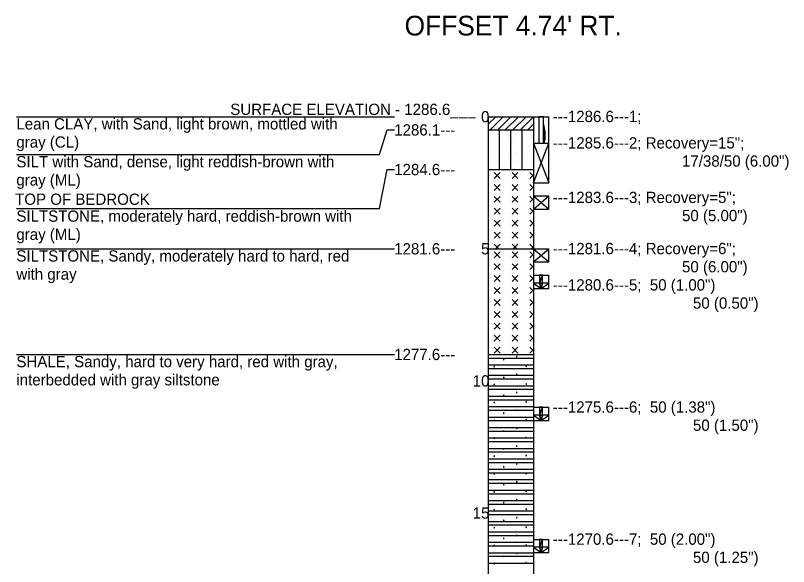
# Model space of a CAD drawing. Extents: x -6 to 173, y 24 to 64.
# Drawn here: x 152.92 to 161.44, y 44.54 to 50.61 of the extents above; entities that cross this region are included whole.
import ezdxf

# ---------------------------------------------------------------- set-up
doc = ezdxf.new("R2010")
doc.units = 0

# ---------------------------------------------------------------- blocks, each defined once
blk = doc.blocks.new('POINT_DISPLAY')
blk.add_line((0, 0), (0, 0))

msp = doc.modelspace()

# ---------------------------------------------------------------- linework, layer by layer
for points in [[(152.9304, 49.4948), (157.097, 49.4948)], [(158.1273, 49.4115), (158.2107, 49.4948)], [(158.1273, 49.4948), (158.794, 49.4948)], [(158.1273, 49.4948), (158.1273, 39.0297)], [(158.1487, 49.3495), (158.294, 49.4948)], [(158.232, 49.3495), (158.3773, 49.4948)], [(158.3153, 49.3495), (158.4607, 49.4948)], [(158.3987, 49.3495), (158.544, 49.4948)], [(158.482, 49.3495), (158.6273, 49.4948)], [(158.6273, 49.4948), (158.6273, 39.0297)], [(158.794, 49.2041), (158.794, 49.4948)], [(158.5653, 49.3495), (158.6273, 49.4115)], [(152.9304, 49.0781), (156.9304, 49.0781), (157.0137, 49.3495), (157.097, 49.3495)], [(158.1273, 49.3495), (158.6273, 49.3495)], [(158.2523, 48.9134), (158.2523, 49.3495)], [(158.3773, 48.9134), (158.3773, 49.3495)], [(158.5023, 48.9134), (158.5023, 49.3495)], [(158.6273, 49.2041), (158.794, 49.2041)], [(158.6273, 49.2041), (158.794, 48.7681)], [(158.6273, 48.7681), (158.794, 49.2041)], [(158.6273, 49.2041), (158.794, 49.2041)], [(158.794, 48.7681), (158.794, 49.2041)], [(152.9304, 48.4833), (156.9304, 48.4833), (157.0137, 48.9134), (157.097, 48.9134)], [(158.1273, 48.9134), (158.6273, 48.9134)], [(158.2586, 48.8806), (158.193, 48.815)], [(158.193, 48.8806), (158.2586, 48.815)], [(158.4554, 48.8806), (158.3898, 48.815)], [(158.3898, 48.8806), (158.4554, 48.815)], [(158.5867, 48.8806), (158.6273, 48.8399)], [(158.6273, 48.8557), (158.5867, 48.815)], [(158.2586, 48.7494), (158.193, 48.6838)], [(158.193, 48.7494), (158.2586, 48.6838)], [(158.4554, 48.7494), (158.3898, 48.6838)], [(158.3898, 48.7494), (158.4554, 48.6838)], [(158.5867, 48.7494), (158.6273, 48.7087)], [(158.6273, 48.7244), (158.5867, 48.6838)], [(158.6273, 48.7681), (158.794, 48.7681)], [(158.2586, 48.6181), (158.193, 48.5525)], [(158.193, 48.6181), (158.2586, 48.5525)], [(158.4554, 48.6181), (158.3898, 48.5525)], [(158.3898, 48.6181), (158.4554, 48.5525)], [(158.5867, 48.6181), (158.6273, 48.5775)], [(158.6273, 48.5932), (158.5867, 48.5525)], [(158.6273, 48.6227), (158.794, 48.4774)], [(158.6273, 48.4774), (158.794, 48.6227)], [(158.6273, 48.6227), (158.794, 48.6227)], [(158.794, 48.4774), (158.794, 48.6227)], [(158.2586, 48.4869), (158.193, 48.4213)], [(158.193, 48.4869), (158.2586, 48.4213)], [(158.4554, 48.4869), (158.3898, 48.4213)], [(158.3898, 48.4869), (158.4554, 48.4213)], [(158.5867, 48.4869), (158.6273, 48.4462)], [(158.6273, 48.462), (158.5867, 48.4213)], [(158.6273, 48.4774), (158.794, 48.4774)], [(158.2586, 48.3557), (158.193, 48.2901)], [(158.193, 48.3557), (158.2586, 48.2901)], [(158.4554, 48.3557), (158.3898, 48.2901)], [(158.3898, 48.3557), (158.4554, 48.2901)], [(158.5867, 48.3557), (158.6273, 48.315)], [(158.6273, 48.3307), (158.5867, 48.2901)], [(158.2586, 48.2244), (158.193, 48.1588)], [(158.193, 48.2244), (158.2586, 48.1588)], [(158.4554, 48.2244), (158.3898, 48.1588)], [(158.3898, 48.2244), (158.4554, 48.1588)], [(158.5867, 48.2244), (158.6273, 48.1838)], [(158.6273, 48.1995), (158.5867, 48.1588)], [(152.9304, 48.0413), (157.097, 48.0413)], [(158.1273, 48.0413), (158.6273, 48.0413)], [(158.193, 48.0932), (158.2448, 48.0413)], [(158.2586, 48.0932), (158.2067, 48.0413)], [(158.3898, 48.0932), (158.4417, 48.0413)], [(158.4554, 48.0932), (158.4035, 48.0413)], [(158.5867, 48.0932), (158.6123, 48.0676), (158.6273, 48.0525)], [(158.6273, 48.0683), (158.6175, 48.0585), (158.6004, 48.0413)], [(158.6273, 48.0413), (158.794, 47.896)], [(158.6273, 47.896), (158.794, 48.0413)], [(158.6273, 48.0413), (158.794, 48.0413)], [(158.794, 47.896), (158.794, 48.0413)], [(158.2586, 48.0085), (158.193, 47.9429)], [(158.193, 48.0085), (158.2586, 47.9429)], [(158.4554, 48.0085), (158.3898, 47.9429)], [(158.3898, 48.0085), (158.4554, 47.9429)], [(158.5867, 48.0085), (158.6273, 47.9678)], [(158.6273, 47.9836), (158.5867, 47.9429)], [(158.2586, 47.8773), (158.193, 47.8117)], [(158.193, 47.8773), (158.2586, 47.8117)], [(158.4554, 47.8773), (158.3898, 47.8117)], [(158.3898, 47.8773), (158.4554, 47.8117)], [(158.5867, 47.8773), (158.6273, 47.8366)], [(158.6273, 47.896), (158.794, 47.896)], [(158.6273, 47.8523), (158.5867, 47.8117)], [(158.2586, 47.7461), (158.193, 47.6804)], [(158.193, 47.7461), (158.2586, 47.6804)], [(158.4554, 47.7461), (158.3898, 47.6804)], [(158.3898, 47.7461), (158.4554, 47.6804)], [(158.5867, 47.7461), (158.6273, 47.7054)], [(158.6273, 47.7211), (158.5867, 47.6804)], [(158.6273, 47.7506), (158.794, 47.7506)], [(158.794, 47.6053), (158.794, 47.7506)], [(158.2586, 47.6148), (158.193, 47.5492)], [(158.193, 47.6148), (158.2586, 47.5492)], [(158.4554, 47.6148), (158.3898, 47.5492)], [(158.3898, 47.6148), (158.4554, 47.5492)], [(158.5867, 47.6148), (158.6273, 47.5741)], [(158.6273, 47.6053), (158.794, 47.6053)], [(158.6273, 47.5899), (158.5867, 47.5492)], [(158.2586, 47.4836), (158.193, 47.418)], [(158.193, 47.4836), (158.2586, 47.418)], [(158.4554, 47.4836), (158.3898, 47.418)], [(158.3898, 47.4836), (158.4554, 47.418)], [(158.5867, 47.4836), (158.6273, 47.4429)], [(158.6273, 47.4586), (158.5867, 47.418)], [(158.2586, 47.3523), (158.193, 47.2867)], [(158.193, 47.3523), (158.2586, 47.2867)], [(158.4554, 47.3523), (158.3898, 47.2867)], [(158.3898, 47.3523), (158.4554, 47.2867)], [(158.5867, 47.3523), (158.6273, 47.3117)], [(158.6273, 47.3274), (158.5867, 47.2867)], [(158.2586, 47.2211), (158.193, 47.1555)], [(158.193, 47.2211), (158.2586, 47.1555)], [(158.4554, 47.2211), (158.3898, 47.1555)], [(158.3898, 47.2211), (158.4554, 47.1555)], [(158.5867, 47.2211), (158.6273, 47.1804)], [(158.6273, 47.1962), (158.5867, 47.1555)], [(158.2586, 47.0899), (158.193, 47.0243)], [(158.193, 47.0899), (158.2586, 47.0243)], [(158.4554, 47.0899), (158.3898, 47.0243)], [(158.3898, 47.0899), (158.4554, 47.0243)], [(158.5867, 47.0899), (158.6273, 47.0492)], [(158.6273, 47.0649), (158.5867, 47.0243)], [(158.2586, 46.9586), (158.193, 46.893)], [(158.193, 46.9586), (158.2586, 46.893)], [(158.4554, 46.9586), (158.3898, 46.893)], [(158.3898, 46.9586), (158.4554, 46.893)], [(158.5867, 46.9586), (158.5976, 46.9477), (158.6273, 46.918)], [(158.6273, 46.9337), (158.6107, 46.9171), (158.5867, 46.893)], [(152.9304, 46.8785), (157.097, 46.8785)], [(158.1273, 46.8785), (158.6273, 46.8785)], [(158.1273, 46.8785), (158.6273, 46.8785)], [(158.1273, 46.8392), (158.6273, 46.8392)], [(158.445, 46.8546), (158.4434, 46.8574), (158.4401, 46.8574), (158.4384, 46.8546), (158.4401, 46.8518), (158.4434, 46.8518), (158.445, 46.8546)], [(158.1273, 46.7637), (158.6273, 46.7637)], [(158.3024, 46.8227), (158.3008, 46.8256), (158.2975, 46.8256), (158.2958, 46.8228), (158.2975, 46.8199), (158.3008, 46.8199), (158.3024, 46.8227)], [(158.5505, 46.7503), (158.5489, 46.7531), (158.5456, 46.7531), (158.5439, 46.7503), (158.5456, 46.7474), (158.5489, 46.7474), (158.5505, 46.7503)], [(158.1273, 46.7243), (158.6273, 46.7243)], [(158.1977, 46.7438), (158.1961, 46.7466), (158.1928, 46.7466), (158.1912, 46.7438), (158.1928, 46.7409), (158.1961, 46.7409), (158.1977, 46.7438)], [(158.1273, 46.6489), (158.6273, 46.6489)], [(158.1273, 46.6095), (158.6273, 46.6095)], [(158.3024, 46.6258), (158.3008, 46.6287), (158.2975, 46.6287), (158.2958, 46.6259), (158.2975, 46.623), (158.3008, 46.623), (158.3024, 46.6258)], [(158.445, 46.6577), (158.4434, 46.6606), (158.4401, 46.6606), (158.4384, 46.6577), (158.4401, 46.6549), (158.4434, 46.6549), (158.445, 46.6577)], [(158.1273, 46.534), (158.6273, 46.534)], [(158.1977, 46.5469), (158.1961, 46.5497), (158.1928, 46.5497), (158.1912, 46.5469), (158.1928, 46.544), (158.1961, 46.544), (158.1977, 46.5469)], [(158.5505, 46.5534), (158.5489, 46.5563), (158.5456, 46.5563), (158.5439, 46.5534), (158.5456, 46.5506), (158.5489, 46.5506), (158.5505, 46.5534)], [(158.1273, 46.4947), (158.6273, 46.4947)], [(158.1273, 46.4192), (158.6273, 46.4192)], [(158.3024, 46.429), (158.3008, 46.4319), (158.2975, 46.4319), (158.2958, 46.4291), (158.2975, 46.4262), (158.3008, 46.4262), (158.3024, 46.429)], [(158.445, 46.4609), (158.4434, 46.4637), (158.4401, 46.4637), (158.4384, 46.4609), (158.4401, 46.4581), (158.4434, 46.4581), (158.445, 46.4609)], [(158.1273, 46.3798), (158.6273, 46.3798)], [(158.1977, 46.3501), (158.1961, 46.3529), (158.1928, 46.3529), (158.1912, 46.3501), (158.1928, 46.3472), (158.1961, 46.3472), (158.1977, 46.3501)], [(158.5505, 46.3566), (158.5489, 46.3594), (158.5456, 46.3594), (158.5439, 46.3566), (158.5456, 46.3537), (158.5489, 46.3537), (158.5505, 46.3566)], [(158.1273, 46.3044), (158.6273, 46.3044)], [(158.1273, 46.265), (158.6273, 46.265)], [(158.445, 46.264), (158.4434, 46.2669), (158.4401, 46.2669), (158.4384, 46.264), (158.4401, 46.2612), (158.4434, 46.2612), (158.445, 46.264)], [(158.6273, 46.2971), (158.794, 46.2971)], [(158.794, 46.1518), (158.794, 46.2971)], [(158.1273, 46.1896), (158.6273, 46.1896)], [(158.1977, 46.1532), (158.1961, 46.156), (158.1928, 46.156), (158.1912, 46.1532), (158.1928, 46.1503), (158.1961, 46.1503), (158.1977, 46.1532)], [(158.3024, 46.2321), (158.3008, 46.235), (158.2975, 46.235), (158.2958, 46.2322), (158.2975, 46.2293), (158.3008, 46.2293), (158.3024, 46.2321)], [(158.5505, 46.1597), (158.5489, 46.1626), (158.5456, 46.1626), (158.5439, 46.1597), (158.5456, 46.1569), (158.5489, 46.1569), (158.5505, 46.1597)], [(158.1273, 46.1502), (158.6273, 46.1502)], [(158.1273, 46.0747), (158.6273, 46.0747)], [(158.445, 46.0672), (158.4434, 46.07), (158.4401, 46.07), (158.4384, 46.0672), (158.4401, 46.0644), (158.4434, 46.0644), (158.445, 46.0672)], [(158.6273, 46.1518), (158.794, 46.1518)], [(158.1273, 46.0354), (158.6273, 46.0354)], [(158.3024, 46.0353), (158.3008, 46.0382), (158.2975, 46.0382), (158.2958, 46.0354), (158.2975, 46.0325), (158.3008, 46.0325), (158.3024, 46.0353)], [(158.1273, 45.9599), (158.6273, 45.9599)], [(158.1273, 45.9205), (158.6273, 45.9205)], [(158.1977, 45.9564), (158.1961, 45.9592), (158.1928, 45.9592), (158.1912, 45.9564), (158.1928, 45.9535), (158.1961, 45.9535), (158.1977, 45.9564)], [(158.5505, 45.9629), (158.5489, 45.9657), (158.5456, 45.9657), (158.5439, 45.9629), (158.5456, 45.96), (158.5489, 45.96), (158.5505, 45.9629)], [(158.1273, 45.8451), (158.6273, 45.8451)], [(158.3024, 45.8384), (158.3008, 45.8413), (158.2975, 45.8413), (158.2958, 45.8385), (158.2975, 45.8356), (158.3008, 45.8356), (158.3024, 45.8384)], [(158.445, 45.8703), (158.4434, 45.8732), (158.4401, 45.8732), (158.4384, 45.8703), (158.4401, 45.8675), (158.4434, 45.8675), (158.445, 45.8703)], [(158.1273, 45.8057), (158.6273, 45.8057)], [(158.1273, 45.7302), (158.6273, 45.7302)], [(158.1977, 45.7595), (158.1961, 45.7623), (158.1928, 45.7623), (158.1912, 45.7595), (158.1928, 45.7566), (158.1961, 45.7566), (158.1977, 45.7595)], [(158.5505, 45.766), (158.5489, 45.7689), (158.5456, 45.7689), (158.5439, 45.766), (158.5456, 45.7632), (158.5489, 45.7632), (158.5505, 45.766)], [(158.1273, 45.6909), (158.6273, 45.6909)], [(158.3024, 45.6416), (158.3008, 45.6445), (158.2975, 45.6445), (158.2958, 45.6417), (158.2975, 45.6388), (158.3008, 45.6388), (158.3024, 45.6416)], [(158.445, 45.6735), (158.4434, 45.6763), (158.4401, 45.6763), (158.4384, 45.6735), (158.4401, 45.6707), (158.4434, 45.6707), (158.445, 45.6735)], [(158.1273, 45.6154), (158.6273, 45.6154)], [(158.1273, 45.576), (158.6273, 45.576)], [(158.1977, 45.5627), (158.1961, 45.5655), (158.1928, 45.5655), (158.1912, 45.5627), (158.1928, 45.5598), (158.1961, 45.5598), (158.1977, 45.5627)], [(158.5505, 45.5692), (158.5489, 45.572), (158.5456, 45.572), (158.5439, 45.5692), (158.5456, 45.5663), (158.5489, 45.5663), (158.5505, 45.5692)], [(158.1273, 45.5006), (158.6273, 45.5006)], [(158.445, 45.4766), (158.4434, 45.4795), (158.4401, 45.4795), (158.4384, 45.4766), (158.4401, 45.4738), (158.4434, 45.4738), (158.445, 45.4766)], [(158.1273, 45.4612), (158.6273, 45.4612)], [(158.3024, 45.4447), (158.3008, 45.4476), (158.2975, 45.4476), (158.2958, 45.4448), (158.2975, 45.4419), (158.3008, 45.4419), (158.3024, 45.4447)], [(158.1273, 45.3858), (158.6273, 45.3858)], [(158.1273, 45.3464), (158.6273, 45.3464)], [(158.1977, 45.3658), (158.1961, 45.3686), (158.1928, 45.3686), (158.1912, 45.3658), (158.1928, 45.3629), (158.1961, 45.3629), (158.1977, 45.3658)], [(158.5505, 45.3723), (158.5489, 45.3752), (158.5456, 45.3752), (158.5439, 45.3723), (158.5456, 45.3695), (158.5489, 45.3695), (158.5505, 45.3723)], [(158.1273, 45.2709), (158.6273, 45.2709)], [(158.1273, 45.2316), (158.6273, 45.2316)], [(158.3024, 45.2479), (158.3008, 45.2508), (158.2975, 45.2508), (158.2958, 45.248), (158.2975, 45.2451), (158.3008, 45.2451), (158.3024, 45.2479)], [(158.445, 45.2798), (158.4434, 45.2826), (158.4401, 45.2826), (158.4384, 45.2798), (158.4401, 45.277), (158.4434, 45.277), (158.445, 45.2798)], [(158.1273, 45.1561), (158.6273, 45.1561)], [(158.1977, 45.169), (158.1961, 45.1718), (158.1928, 45.1718), (158.1912, 45.169), (158.1928, 45.1661), (158.1961, 45.1661), (158.1977, 45.169)], [(158.5505, 45.1755), (158.5489, 45.1783), (158.5456, 45.1783), (158.5439, 45.1755), (158.5456, 45.1726), (158.5489, 45.1726), (158.5505, 45.1755)], [(158.1273, 45.1167), (158.6273, 45.1167)], [(158.3024, 45.051), (158.3008, 45.0539), (158.2975, 45.0539), (158.2958, 45.0511), (158.2975, 45.0482), (158.3008, 45.0482), (158.3024, 45.051)], [(158.445, 45.0829), (158.4434, 45.0858), (158.4401, 45.0858), (158.4384, 45.0829), (158.4401, 45.0801), (158.4434, 45.0801), (158.445, 45.0829)], [(158.1273, 45.0413), (158.6273, 45.0413)], [(158.1273, 45.0019), (158.6273, 45.0019)], [(158.1977, 44.9721), (158.1961, 44.9749), (158.1928, 44.9749), (158.1912, 44.9721), (158.1928, 44.9692), (158.1961, 44.9692), (158.1977, 44.9721)], [(158.5505, 44.9786), (158.5489, 44.9815), (158.5456, 44.9815), (158.5439, 44.9786), (158.5456, 44.9758), (158.5489, 44.9758), (158.5505, 44.9786)], [(158.1273, 44.9264), (158.6273, 44.9264)], [(158.1273, 44.8871), (158.6273, 44.8871)], [(158.445, 44.8861), (158.4434, 44.8889), (158.4401, 44.8889), (158.4384, 44.8861), (158.4401, 44.8833), (158.4434, 44.8833), (158.445, 44.8861)], [(158.1273, 44.8116), (158.6273, 44.8116)], [(158.3024, 44.8542), (158.3008, 44.8571), (158.2975, 44.8571), (158.2958, 44.8543), (158.2975, 44.8514), (158.3008, 44.8514), (158.3024, 44.8542)], [(158.6273, 44.8437), (158.794, 44.8437)], [(158.794, 44.6983), (158.794, 44.8437)], [(158.1273, 44.7722), (158.6273, 44.7722)], [(158.1977, 44.7753), (158.1961, 44.7781), (158.1928, 44.7781), (158.1912, 44.7753), (158.1928, 44.7724), (158.1961, 44.7724), (158.1977, 44.7753)], [(158.5505, 44.7818), (158.5489, 44.7846), (158.5456, 44.7846), (158.5439, 44.7818), (158.5456, 44.7789), (158.5489, 44.7789), (158.5505, 44.7818)], [(158.1273, 44.6968), (158.6273, 44.6968)], [(158.1273, 44.6574), (158.6273, 44.6574)], [(158.3024, 44.6573), (158.3008, 44.6602), (158.2975, 44.6602), (158.2958, 44.6574), (158.2975, 44.6545), (158.3008, 44.6545), (158.3024, 44.6573)], [(158.445, 44.6892), (158.4434, 44.6921), (158.4401, 44.6921), (158.4384, 44.6892), (158.4401, 44.6864), (158.4434, 44.6864), (158.445, 44.6892)], [(158.6273, 44.6983), (158.794, 44.6983)], [(158.1273, 44.5819), (158.6273, 44.5819)], [(158.1977, 44.5784), (158.1961, 44.5812), (158.1928, 44.5812), (158.1912, 44.5784), (158.1928, 44.5755), (158.1961, 44.5755), (158.1977, 44.5784)], [(158.5505, 44.5849), (158.5489, 44.5878), (158.5456, 44.5878), (158.5439, 44.5849), (158.5456, 44.5821), (158.5489, 44.5821), (158.5505, 44.5849)]]:
    msp.add_lwpolyline(points)
for points in [[(158.6857, 49.4948), (158.6857, 49.2041), (158.7357, 49.2041), (158.7357, 49.4948)], [(158.7503, 49.3281), (158.7443, 49.3698), (158.7357, 49.4098), (158.7503, 49.3281)], [(158.7357, 49.4098), (158.7357, 49.2041), (158.7503, 49.3281), (158.7357, 49.4098)], [(158.7357, 49.2041), (158.7503, 49.2448), (158.7503, 49.3281), (158.7357, 49.2041)], [(158.7503, 49.2448), (158.7523, 49.2865), (158.7503, 49.3281), (158.7503, 49.2448)], [(158.7357, 49.2041), (158.7445, 49.2041), (158.7503, 49.2448), (158.7357, 49.2041)], [(158.694, 47.6634), (158.7273, 47.6634), (158.7273, 47.7506), (158.694, 47.6634)], [(158.694, 47.6634), (158.7273, 47.7506), (158.694, 47.7506), (158.694, 47.6634)], [(158.694, 47.6634), (158.6273, 47.6634), (158.7107, 47.6053), (158.694, 47.6634)], [(158.694, 47.6634), (158.7107, 47.6053), (158.7273, 47.6634), (158.694, 47.6634)], [(158.7107, 47.6053), (158.794, 47.6634), (158.7273, 47.6634), (158.7107, 47.6053)], [(158.694, 46.2099), (158.7273, 46.2099), (158.7273, 46.2971), (158.694, 46.2099)], [(158.694, 46.2099), (158.7273, 46.2971), (158.694, 46.2971), (158.694, 46.2099)], [(158.694, 46.2099), (158.6273, 46.2099), (158.7107, 46.1518), (158.694, 46.2099)], [(158.694, 46.2099), (158.7107, 46.1518), (158.7273, 46.2099), (158.694, 46.2099)], [(158.7107, 46.1518), (158.794, 46.2099), (158.7273, 46.2099), (158.7107, 46.1518)], [(158.694, 44.7564), (158.7273, 44.7564), (158.7273, 44.8437), (158.694, 44.7564)], [(158.694, 44.7564), (158.7273, 44.8437), (158.694, 44.8437), (158.694, 44.7564)], [(158.694, 44.7564), (158.6273, 44.7564), (158.7107, 44.6983), (158.694, 44.7564)], [(158.694, 44.7564), (158.7107, 44.6983), (158.7273, 44.7564), (158.694, 44.7564)], [(158.7107, 44.6983), (158.794, 44.7564), (158.7273, 44.7564), (158.7107, 44.6983)]]:
    msp.add_lwpolyline(points, close=True)

# ---------------------------------------------------------------- block references
at = {"xscale": 0.01, "yscale": 0.01}
for p in [(158.1665, 49.4781), (158.3332, 49.4781), (158.1332, 49.4115), (158.2332, 49.4448), (158.3561, 49.4145), (158.4332, 49.4448), (158.5529, 49.4615), (158.5998, 49.4115), (158.1665, 49.3328), (158.1998, 49.3781), (158.3332, 49.3328), (158.3998, 49.3781), (158.4998, 49.3781), (158.5529, 49.3161), (158.1332, 49.2661), (158.1998, 49.2328), (158.2332, 49.2995), (158.3561, 49.2692), (158.3998, 49.2328), (158.4332, 49.2995), (158.4998, 49.2328), (158.5998, 49.2661), (158.1665, 49.1661), (158.2665, 49.1995), (158.4167, 49.157), (158.5665, 49.1661), (158.1998, 49.0995), (158.2665, 49.0661), (158.3332, 49.1328), (158.3516, 49.0555), (158.4332, 49.0995), (158.5513, 49.0813), (158.1332, 49.0328), (158.2332, 48.9995), (158.2998, 48.9661), (158.403, 48.9858), (158.4665, 48.9995), (158.5332, 48.9661), (158.5998, 49.0328), (158.3665, 48.9328)]:
    msp.add_blockref('POINT_DISPLAY', p, dxfattribs=at)

# ---------------------------------------------------------------- texts
for s, height, p in [("OFFSET 4.74' RT.", 0.217, (157.2064, 50.3884)), ('SURFACE ELEVATION - 1286.6___', 0.124, (155.2867, 49.5139)), ('---1286.6---1;', 0.124, (158.8393, 49.4355)), ('Lean CLAY, with Sand, light brown, mottled with', 0.124, (152.9304, 49.3541)), ('0', 0.124, (158.049, 49.4328)), ('1286.1---', 0.124, (157.0921, 49.2875)), ('gray (CL)', 0.124, (152.9304, 49.1541)), ('---1285.6---2; Recovery=15";', 0.124, (158.8393, 49.1448)), ('SILT with Sand, dense, light reddish-brown with', 0.124, (152.9304, 48.9375)), ('17/38/50 (6.00")', 0.124, (160.2625, 48.9448)), ('1284.6---', 0.124, (157.0921, 48.8514)), ('gray (ML)', 0.124, (152.9304, 48.7375)), ('TOP OF BEDROCK', 0.124, (152.9166, 48.5247)), ('---1283.6---3; Recovery=5";', 0.124, (158.8393, 48.5448)), ('SILTSTONE, moderately hard, reddish-brown with', 0.124, (152.9304, 48.339)), ('50 (5.00")', 0.124, (160.2625, 48.3448)), ('gray (ML)', 0.124, (152.9304, 48.139)), ('SILTSTONE, Sandy, moderately hard to hard, red', 0.124, (152.9304, 47.9007)), ('1281.6---', 0.124, (157.0921, 47.9793)), ('5', 0.124, (158.049, 47.9793)), ('---1281.6---4; Recovery=6";', 0.124, (158.8393, 47.982)), ('50 (6.00")', 0.124, (160.2625, 47.782)), ('with gray', 0.124, (152.9304, 47.7007)), ('---1280.6---5;  50 (1.00")', 0.124, (158.8393, 47.582)), ('50 (0.50")', 0.124, (160.383, 47.382)), ('1277.6---', 0.124, (157.0921, 46.8165)), ('SHALE, Sandy, hard to very hard, red with gray,', 0.124, (152.9304, 46.7379)), ('interbedded with gray siltstone', 0.124, (152.9304, 46.5379)), ('10', 0.124, (157.9569, 46.5258)), ('---1275.6---6;  50 (1.38")', 0.124, (158.8393, 46.2378)), ('50 (1.50")', 0.124, (160.383, 46.0378)), ('15', 0.124, (157.9569, 45.0723)), ('---1270.6---7;  50 (2.00")', 0.124, (158.8393, 44.7843)), ('50 (1.25")', 0.124, (160.383, 44.5843))]:
    msp.add_text(s, height=height).set_placement(p)

doc.saveas('drawing.dxf')
